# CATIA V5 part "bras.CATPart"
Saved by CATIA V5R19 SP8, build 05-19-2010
Part number: bras1
Publications: "longueur_bras1", "longueur_lumière"
Bounding box of the stored display mesh (mm): x 0 to 10, y -620 to 20, z 0 to 40
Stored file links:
  G:\EU_thinkMotion\CFAO_2010\SIL_groupe1\SIL_groupe1\A reprendre\fbruguiere\fbruguiere\fbruguiere\bras.CATPart
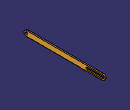
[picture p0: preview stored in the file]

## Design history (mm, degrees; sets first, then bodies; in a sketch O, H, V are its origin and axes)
Parameters
  longueur_bras1 = 600
  `longueur_lumière` = 120
Body1 (main body)
  Sketch1 on yz-plane, origin (0, 0, 0), H (0, 1, 0), V (0, 0, 1)
    line L1 (0, 0) -> (-600, 0)
    line L2 (-600, 40) -> (0, 40)
    arc A1 centre (-600, 20) radius 20 from (-600, 40) to (-600, 0) ccw
    arc A2 centre (0, 20) radius 20 from (0, 0) to (0, 40) ccw
    length L1 = 600 {= longueur_bras1 *1mm}
    distance L2 L1 = 40
    radius A1 = 20
    horizontal: L1 H, L2 H
    tangency: A1 L1, A2 L1
  Pad1: profile Sketch1, direction (1, 0, 0), length 10
  Sketch2 on end face of Pad1, origin (10, 0, 0), H (0, 1, 0), V (0, 0, 1)
    circle A1 centre (-600, 20) radius 10
    arc A2 centre (0, 20) radius 10 from (-0.387, 10.0075) to (-0.3981, 29.9921) ccw
    point P2 (0, 20)
    arc A3 centre (-120, 20.0015) radius 10 from (-120, 30.0015) to (-119.9995, 10.0015) ccw
    point P3 (-120, 20.0015)
    line L1 (-120, 30.0015) -> (-0.3981, 29.9921)
    line L2 (-0.387, 10.0075) -> (-119.9995, 10.0015)
    radius A2 = 10
    radius A3 = 10
    distance P3 P2 = 120 {= `longueur_lumière` *1mm}
    coincidence: P2 V
    tangency: L2 A3
  Pocket1: profile Sketch2, direction (-1, 0, 0), through (limit type 6)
